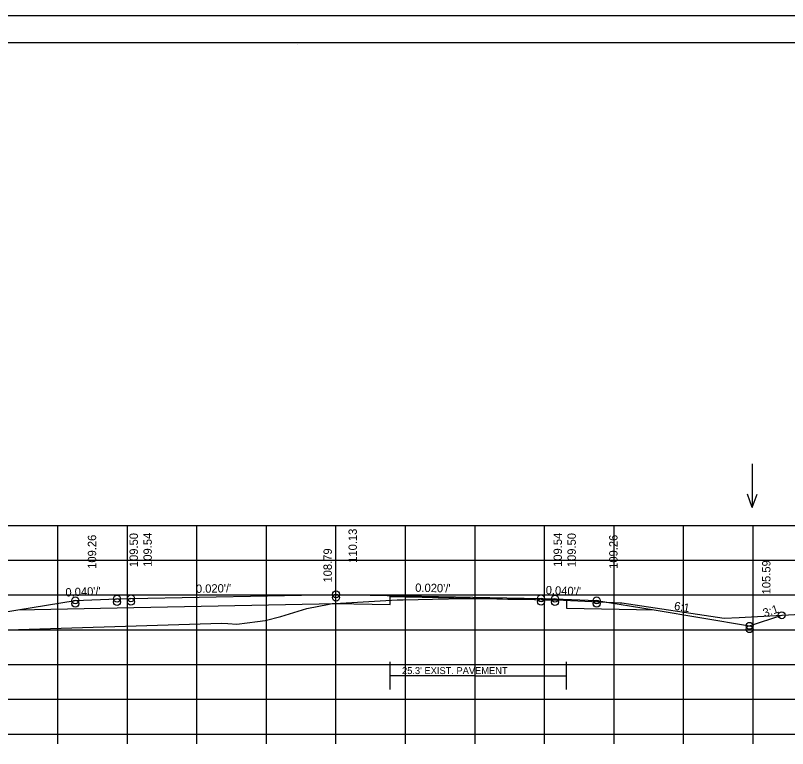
# Model space of a CAD drawing. Extents: x 1175611 to 1176402, y -433344 to -416213.
# Drawn here: x 1175734.9 to 1175845.9, y -432168.9 to -432063.5 of the extents above; entities that cross this region are included whole.
import ezdxf

# ---------------------------------------------------------------- set-up
doc = ezdxf.new("R2010")
doc.units = 0
for name, color, linetype in [('R_Alt Surface', 7, 'Continuous'), ('R_Axis', 7, 'Continuous'), ('R_Border', 7, 'Continuous'), ('R_Draft', 7, 'Continuous'), ('R_Exist Surface', 7, 'Continuous'), ('R_Fin Surface', 7, 'Continuous'), ('R_Grid', 7, 'Continuous'), ('R_No Plot', 7, 'Continuous'), ('R_Water Annot', 7, 'Continuous'), ('R_Xsect Elev', 7, 'Continuous'), ('R_Xsect Slope', 7, 'Continuous')]:
    doc.layers.add(name, color=color, linetype=linetype)

msp = doc.modelspace()

# ---------------------------------------------------------------- linework, layer by layer
at = {"layer": 'R_Alt Surface'}
msp.add_lwpolyline([(1175735.2, -432149.02), (1175749.47, -432148.73), (1175780.97, -432148.1), (1175788.78, -432148.25), (1175788.78, -432147.09), (1175814.11, -432147.6), (1175814.11, -432148.76), (1175826.75, -432149.02)], dxfattribs=at)
at = {"layer": 'R_Axis'}
for p, q in [((1175640.97, -432166.86), (1175920.97, -432166.86)), ((1175740.97, -432168.26), (1175740.97, -432166.86)), ((1175750.97, -432168.26), (1175750.97, -432166.86)), ((1175760.97, -432168.26), (1175760.97, -432166.86)), ((1175770.97, -432168.26), (1175770.97, -432166.86)), ((1175780.97, -432168.26), (1175780.97, -432166.86)), ((1175790.97, -432168.26), (1175790.97, -432166.86)), ((1175800.97, -432168.26), (1175800.97, -432166.86)), ((1175810.97, -432168.26), (1175810.97, -432166.86)), ((1175820.97, -432168.26), (1175820.97, -432166.86)), ((1175830.97, -432168.26), (1175830.97, -432166.86)), ((1175840.97, -432168.26), (1175840.97, -432166.86))]:
    msp.add_line(p, q, dxfattribs=at)
at = {"layer": 'R_Border'}
for p, q in [((1175622.97, -432067.4), (1175939.15, -432067.4)), ((1175775.49, -432067.66), (1175775.49, -432067.66)), ((1175775.49, -432067.66), (1175775.49, -432067.66))]:
    msp.add_line(p, q, dxfattribs=at)
at = {"layer": 'R_Draft'}
for q in [(1175788.78, -432158.47), (1175814.11, -432158.47)]:
    msp.add_line((1175800.96, -432158.47), q, dxfattribs=at)
for points in [[(1175788.78, -432160.47), (1175788.78, -432156.47)], [(1175814.11, -432160.47), (1175814.11, -432156.47)]]:
    msp.add_lwpolyline(points, dxfattribs=at)
at = {"layer": 'R_Exist Surface'}
msp.add_lwpolyline([(1175729.13, -432152.03), (1175764.52, -432150.9), (1175765.39, -432150.97), (1175766.72, -432151.04), (1175769.69, -432150.68), (1175770.78, -432150.54), (1175773.04, -432149.94), (1175776.79, -432148.8), (1175780, -432148.16), (1175780.12, -432148.13), (1175780.19, -432148.12), (1175780.44, -432148.11), (1175780.78, -432148.09), (1175789.75, -432147.58), (1175790.62, -432147.57), (1175792.77, -432147.53), (1175794.86, -432147.48), (1175799.5, -432147.37), (1175800.01, -432147.35), (1175800.88, -432147.36), (1175800.96, -432147.36), (1175801.52, -432147.36), (1175802.83, -432147.36), (1175803.15, -432147.38), (1175804.1, -432147.43), (1175805.71, -432147.45), (1175808.97, -432147.48), (1175809.68, -432147.51), (1175811.03, -432147.56), (1175811.61, -432147.56), (1175812.68, -432147.56), (1175821.84, -432147.97), (1175821.99, -432147.97), (1175822.03, -432147.97), (1175822.11, -432147.99), (1175836.8, -432150.21), (1175838.98, -432150.08), (1175850.48, -432149.49)], dxfattribs=at)
at = {"layer": 'R_Fin Surface'}
msp.add_lwpolyline([(1175719.2, -432152.06), (1175721.47, -432151.3), (1175735.2, -432149.02), (1175743.47, -432147.64), (1175749.47, -432147.4), (1175751.47, -432147.36), (1175780.97, -432146.77), (1175810.47, -432147.36), (1175812.47, -432147.4), (1175818.47, -432147.64), (1175826.75, -432149.02), (1175840.47, -432151.3), (1175845.09, -432149.77)], dxfattribs=at)
msp.add_lwpolyline([(1175719.2, -432152.06), (1175721.47, -432151.3), (1175735.2, -432149.02), (1175743.47, -432147.64), (1175749.47, -432147.4), (1175751.47, -432147.36), (1175780.97, -432146.77), (1175810.47, -432147.36), (1175812.47, -432147.4), (1175818.47, -432147.64), (1175826.75, -432149.02), (1175840.47, -432151.3), (1175845.09, -432149.77)], dxfattribs=at)
at = {"layer": 'R_Grid'}
for p, q in [((1175640.97, -432136.86), (1175920.97, -432136.86)), ((1175740.97, -432166.86), (1175740.97, -432136.86)), ((1175750.97, -432166.86), (1175750.97, -432136.86)), ((1175760.97, -432166.86), (1175760.97, -432136.86)), ((1175770.97, -432166.86), (1175770.97, -432136.86)), ((1175780.97, -432166.86), (1175780.97, -432136.86)), ((1175790.97, -432166.86), (1175790.97, -432136.86)), ((1175800.97, -432166.86), (1175800.97, -432136.86)), ((1175810.97, -432166.86), (1175810.97, -432136.86)), ((1175820.97, -432166.86), (1175820.97, -432136.86)), ((1175830.97, -432166.86), (1175830.97, -432136.86)), ((1175840.97, -432166.86), (1175840.97, -432136.86)), ((1175640.97, -432141.86), (1175920.97, -432141.86)), ((1175640.97, -432146.86), (1175920.97, -432146.86)), ((1175640.97, -432151.86), (1175920.97, -432151.86)), ((1175640.97, -432156.86), (1175920.97, -432156.86)), ((1175640.97, -432161.86), (1175920.97, -432161.86)), ((1175640.97, -432166.86), (1175920.97, -432166.86))]:
    msp.add_line(p, q, dxfattribs=at)
at = {"layer": 'R_No Plot'}
msp.add_line((1175610.57, -432063.51), (1175943.91, -432063.51), dxfattribs=at)
msp.add_lwpolyline([(1175610.57, -432063.51), (1175943.91, -432063.51), (1175943.91, -432276.84), (1175610.57, -432276.84)], close=True, dxfattribs=at)
for centre in [(1175749.47, -432147.4), (1175751.47, -432147.36), (1175780.97, -432146.77), (1175780.97, -432147.24), (1175810.47, -432147.36), (1175812.47, -432147.4), (1175743.47, -432147.64), (1175743.47, -432148.11), (1175749.47, -432147.87), (1175751.47, -432147.83), (1175810.47, -432147.83), (1175812.47, -432147.87), (1175818.47, -432147.64), (1175818.47, -432148.11), (1175845.09, -432149.77), (1175845.09, -432149.77), (1175840.47, -432151.3), (1175840.47, -432151.3), (1175840.47, -432151.78)]:
    msp.add_circle(centre, 0.5, dxfattribs=at)
at = {"layer": 'R_Water Annot'}
for p, q in [((1175840.86, -432127.98), (1175840.86, -432134.26)), ((1175840.86, -432134.26), (1175840.16, -432132.34)), ((1175840.86, -432134.26), (1175841.56, -432132.34))]:
    msp.add_line(p, q, dxfattribs=at)

# ---------------------------------------------------------------- texts
at = {"layer": 'R_Draft'}
msp.add_text("25.3' EXIST. PAVEMENT", height=1, dxfattribs=at).set_placement((1175790.47, -432158.24))
at = {"layer": 'R_Xsect Elev'}
for s, p in [('109.50', (1175752.47, -432142.86)), ('109.54', (1175754.47, -432142.82)), ('110.13', (1175783.97, -432142.23)), ('109.54', (1175813.47, -432142.82)), ('109.50', (1175815.47, -432142.86)), ('109.26', (1175746.47, -432143.1)), ('109.26', (1175821.47, -432143.1)), ('108.79', (1175780.37, -432145.07)), ('105.59', (1175843.47, -432146.77))]:
    msp.add_text(s, height=1.2, rotation=90, dxfattribs=at).set_placement(p)
at = {"layer": 'R_Xsect Slope'}
for s, rotation, p in [("0.040'/'", 2.2906, (1175742.07, -432147.09)), ("0.020'/'", 1.1458, (1175760.83, -432146.57)), ("0.020'/'", 358.8542, (1175792.36, -432146.4)), ("0.040'/'", 357.7094, (1175811.12, -432146.74)), ('6:1', 350.5377, (1175829.55, -432148.98)), ('3:1', 18.4349, (1175842.62, -432150.06))]:
    msp.add_text(s, height=1.2, rotation=rotation, dxfattribs=at).set_placement(p)

doc.saveas('drawing.dxf')
